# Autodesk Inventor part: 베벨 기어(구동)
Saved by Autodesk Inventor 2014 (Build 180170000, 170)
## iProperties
Created: 2026-01
Part Number: 베벨 기어(구동)
Material: 일반
Document SubType Name: Modeling
Designer: dg
Density: 1 g/cm^3
Appearance: 기본값
Author: dg
Author: jhkim
Creation Date: 2026-01-09
Sending System: Autodesk Inventor 2026
Preprocessor: ST-DEVELOPER v20.1
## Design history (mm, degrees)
node "베벨 기어(구동)1"
body "Solid1"
node "기준1"
